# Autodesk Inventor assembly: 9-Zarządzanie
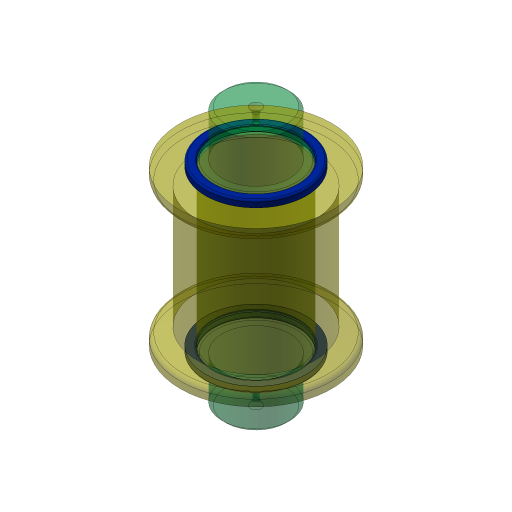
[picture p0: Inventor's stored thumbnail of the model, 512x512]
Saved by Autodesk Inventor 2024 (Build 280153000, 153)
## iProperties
Created: 2023-03
Part Number: 9-Zarządzanie
Document SubType Name: Assembly
Designer: Andrzej Jaskulski
Checked By: A.J.
Engr Approved By: Andrzej Jaskulski
Mfg Approved By: Andrzej Jaskulski
Authority: A.J.
Company: ATC
Control State: 0
Master: False
Checked Out: False
Shininess: 20.0
Length Units: 11269
Angle Units: 11279
Time Units: 11290
Mass Units: 11283
Length Display Precision: 3
Angle Display Precision: 2
Compacted: True
Density: 0.0
Volumn: 0.0
Area: 0.0
PropertySet Name: Model Information
Title: A.J.: Kurs R2024-MEP
Author: Andrzej Jaskulski
Revision Number: 1/24
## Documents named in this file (4)
- C:\Users\AndJas\Documents\R2024-MEP\Obszar roboczy\9-Zarządzanie.iam
- C:\Users\AndJas\Documents\R2024-MEP\Obszar roboczy\Część1.ipt
- C:\Users\AndJas\Documents\R2024-MEP\Obszar roboczy\Część2.ipt
- C:\Users\AndJas\Documents\R2024-MEP\Obszar roboczy\Część3.ipt
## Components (4 placed, 3 different names)
1. WaŁeK:1 — Wstawiające:3
2. PoDkŁaDkA:1 — Wstawiające:2, Wstawiające:3
3. PoDkŁaDkA:2 — Wstawiające:1
4. RoLkA:1 — Wstawiające:1, Wstawiające:2
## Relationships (3: Insert 3)
- Wstawiające:1 [Insert]: PoDkŁaDkA:2 ↔ RoLkA:1
- Wstawiające:2 [Insert]: PoDkŁaDkA:1 ↔ RoLkA:1
- Wstawiające:3 [Insert]: WaŁeK:1 ↔ PoDkŁaDkA:1
